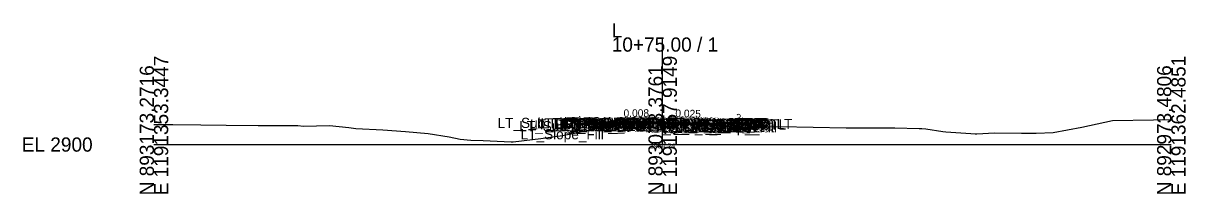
# Model space of a CAD drawing. Extents: x -26 to 203, y -10 to 7027.
# Drawn here: x -25.7 to 202.8, y 1490.3 to 1523.9 of the extents above; entities that cross this region are included whole.
import ezdxf

# ---------------------------------------------------------------- set-up
doc = ezdxf.new("R2010")
doc.units = 0
for name, color, linetype in [('Default', 7, 'Continuous'), ('Exist CMT Pavement', 7, 'Continuous'), ('Exist Cross Section Cell', 7, 'Continuous'), ('Exist XS Center Line Elevation Label', 7, 'Continuous'), ('Exist XS Ground Line', 7, 'Continuous'), ('Prop CMT Concrete Structures', 7, 'Continuous'), ('Prop CMT Pvmt Course 1', 7, 'Continuous'), ('Prop CMT Pvmt Course 2', 7, 'Continuous'), ('Prop CMT Pvmt Course 2 Wedge', 7, 'Continuous'), ('Prop CMT Pvmt Course 3', 7, 'Continuous'), ('Prop CMT Pvmt Course 3 Wedge', 7, 'Continuous'), ('Prop CMT Pvmt Surface', 7, 'Continuous'), ('Prop CMT Pvmt Surface Shoulder', 7, 'Continuous'), ('Prop CMT Pvmt Wedge Surface 3', 7, 'Continuous'), ('Prop CMT Shld Paved Course 1', 7, 'Continuous'), ('Prop CMT Shld Paved Course 2', 7, 'Continuous'), ('Prop CMT Shld Paved Course 3', 7, 'Continuous'), ('Prop CMT Slope Grass', 7, 'Continuous'), ('Prop CMT Subgrade Earthwork', 7, 'Continuous'), ('Scratch_Level_6', 7, 'Continuous')]:
    doc.layers.add(name, color=color, linetype=linetype)

msp = doc.modelspace()

# ---------------------------------------------------------------- linework, layer by layer
at = {"layer": 'Exist CMT Pavement'}
for points in [[(89.88, 1504.19), (88.67, 1504.18), (88.46, 1503.97)], [(88.46, 1503.97), (89.88, 1503.98)], [(89.88, 1503.98), (89.88, 1504.19)], [(100, 1504.24), (91.04, 1504.19)], [(91.04, 1504.19), (95.52, 1504.21)], [(95.52, 1504.21), (100, 1504.24)], [(104.73, 1504.09), (100, 1504.24)], [(100, 1504.24), (109.47, 1503.95)], [(109.47, 1503.95), (104.73, 1504.09)], [(110.13, 1504.02), (111.34, 1503.99), (111.55, 1503.78)], [(110.13, 1503.81), (110.13, 1504.02)], [(111.55, 1503.78), (110.13, 1503.81)]]:
    msp.add_lwpolyline(points, dxfattribs=at)
at = {"layer": 'Exist Cross Section Cell'}
for p, q in [((100, 1500), (100, 1521.09)), ((0, 1500), (100, 1500)), ((100, 1500), (200, 1500))]:
    msp.add_line(p, q, dxfattribs=at)
at = {"layer": 'Exist XS Center Line Elevation Label'}
for points in [[(100, 1504.27), (91.04, 1504.2)], [(100, 1504.27), (109.47, 1504.04)]]:
    msp.add_lwpolyline(points, dxfattribs=at)
at = {"layer": 'Exist XS Ground Line'}
for points in [[(100, 1504.36), (91.04, 1504.28)], [(100, 1504.36), (109.47, 1504.12)]]:
    msp.add_lwpolyline(points, dxfattribs=at)
at = {"layer": 'Prop CMT Concrete Structures'}
for points in [[(100, 1504.48), (89.88, 1504.4)], [(100, 1504.48), (110.13, 1504.23)]]:
    msp.add_lwpolyline(points, dxfattribs=at)
at = {"layer": 'Prop CMT Pvmt Course 1'}
for points in [[(100, 1504.48), (89.88, 1504.4)], [(89.88, 1504.4), (89.88, 1504.19)], [(89.88, 1504.19), (91.04, 1504.2)], [(91.04, 1504.2), (89.88, 1504.19)], [(89.88, 1504.19), (89.88, 1503.98)], [(89.88, 1503.98), (91.04, 1503.99)], [(91.04, 1504.28), (100, 1504.36)], [(91.04, 1504.2), (91.04, 1504.28)], [(91.04, 1503.99), (91.04, 1504.2)], [(100, 1504.27), (100, 1504.48)], [(100, 1504.48), (110.13, 1504.23)], [(100, 1504.27), (100, 1504.48)], [(100, 1504.36), (100, 1504.27), (100, 1504.27)], [(109.47, 1504.12), (100, 1504.36)], [(100, 1504.36), (100, 1504.27), (100, 1504.27)], [(109.47, 1504.04), (109.47, 1504.12)], [(110.13, 1504.02), (109.47, 1504.04)], [(109.47, 1503.83), (109.47, 1504.04)], [(109.47, 1504.04), (110.13, 1504.02)], [(110.13, 1503.81), (109.47, 1503.83)], [(110.13, 1504.23), (110.13, 1504.02)], [(110.13, 1504.02), (110.13, 1503.81)]]:
    msp.add_lwpolyline(points, dxfattribs=at)
at = {"layer": 'Prop CMT Pvmt Course 2'}
for points in [[(100, 1504.06), (91.04, 1503.99)], [(100, 1504.06), (109.47, 1503.83)]]:
    msp.add_lwpolyline(points, dxfattribs=at)
at = {"layer": 'Prop CMT Pvmt Course 3'}
for points in [[(91.04, 1503.99), (89.88, 1503.98)], [(89.88, 1503.98), (89.88, 1503.65)], [(91.04, 1503.66), (91.04, 1503.99)], [(109.47, 1503.83), (110.13, 1503.81)], [(109.47, 1503.49), (109.47, 1503.83)], [(110.13, 1503.81), (110.13, 1503.48)], [(89.88, 1503.65), (91.04, 1503.66)], [(110.13, 1503.48), (109.47, 1503.49)]]:
    msp.add_lwpolyline(points, dxfattribs=at)
at = {"layer": 'Prop CMT Pvmt Course 3 Wedge'}
for p, q in [((0, 1503.92), (3.7, 1503.97)), ((3.7, 1503.97), (9.2, 1503.91)), ((9.2, 1503.91), (14.23, 1503.81)), ((14.23, 1503.81), (20.5, 1503.78)), ((20.5, 1503.78), (27.45, 1503.73)), ((88.96, 1503.67), (91.04, 1504.19)), ((91.04, 1504.19), (94.71, 1504.21)), ((94.71, 1504.21), (99.89, 1504.24)), ((99.89, 1504.24), (105.8, 1504.06)), ((105.8, 1504.06), (109.47, 1503.95)), ((109.47, 1503.95), (112.43, 1503.58)), ((182.43, 1503.44), (188.44, 1504.74)), ((188.44, 1504.74), (196.51, 1504.89)), ((196.51, 1504.89), (198.34, 1504.91)), ((198.34, 1504.91), (200, 1504.89)), ((27.45, 1503.73), (28.31, 1503.72)), ((28.31, 1503.72), (29.37, 1503.64)), ((29.37, 1503.64), (34.53, 1503.73)), ((34.53, 1503.73), (38.29, 1503.39)), ((38.29, 1503.39), (39.66, 1503.16)), ((39.66, 1503.16), (44.97, 1502.9)), ((44.97, 1502.9), (49.43, 1502.54)), ((49.43, 1502.54), (53.9, 1502.19)), ((53.9, 1502.19), (58.06, 1501.53)), ((58.06, 1501.53), (60.17, 1501.07)), ((76.03, 1501.16), (80.34, 1501.79)), ((80.34, 1501.79), (86.36, 1502.99)), ((86.36, 1502.99), (87.56, 1503.34)), ((87.56, 1503.34), (88.96, 1503.67)), ((112.43, 1503.58), (113.77, 1503.4)), ((113.77, 1503.4), (123.08, 1503.55)), ((123.08, 1503.55), (136.07, 1503.3)), ((136.07, 1503.3), (145.66, 1503.26)), ((145.66, 1503.26), (150.46, 1503.18)), ((150.46, 1503.18), (150.97, 1503.15)), ((150.97, 1503.15), (151.77, 1503.1)), ((151.77, 1503.1), (155.1, 1502.6)), ((155.1, 1502.6), (155.68, 1502.52)), ((155.68, 1502.52), (160.61, 1502.18)), ((160.61, 1502.18), (161.42, 1502.13)), ((161.42, 1502.13), (161.74, 1502.14)), ((161.74, 1502.14), (165.24, 1502.28)), ((165.24, 1502.28), (170.53, 1502.24)), ((170.53, 1502.24), (172.13, 1502.23)), ((172.13, 1502.23), (173.46, 1502.27)), ((173.46, 1502.27), (176.77, 1502.36)), ((176.77, 1502.36), (182.43, 1503.44)), ((60.17, 1501.07), (62.27, 1500.89)), ((62.27, 1500.89), (64.74, 1500.77)), ((64.74, 1500.77), (70.22, 1500.55)), ((70.22, 1500.55), (70.61, 1500.53)), ((70.61, 1500.53), (76.03, 1501.16))]:
    msp.add_line(p, q, dxfattribs=at)
at = {"layer": 'Prop CMT Pvmt Surface'}
for points in [[(88.88, 1504.39), (85.88, 1504.19), (81.56, 1502.03)], [(111.13, 1504.2), (114.13, 1503.96), (115.21, 1503.42)]]:
    msp.add_lwpolyline(points, dxfattribs=at)
at = {"layer": 'Prop CMT Pvmt Surface Shoulder'}
for points in [[(89.88, 1504.4), (88.88, 1504.39)], [(110.13, 1504.23), (111.13, 1504.2)]]:
    msp.add_lwpolyline(points, dxfattribs=at)
at = {"layer": 'Prop CMT Shld Paved Course 1'}
for points in [[(89.88, 1504.4), (88.88, 1504.39), (88.67, 1504.18)], [(88.67, 1504.18), (89.88, 1504.19)], [(89.88, 1504.19), (89.88, 1504.4)], [(89.88, 1504.19), (89.88, 1504.4)], [(91.04, 1504.2), (89.88, 1504.19)], [(100, 1504.36), (91.04, 1504.28)], [(91.04, 1504.28), (91.04, 1504.2)], [(100, 1504.36), (109.47, 1504.12)], [(109.47, 1504.12), (109.47, 1504.04)], [(109.47, 1504.04), (110.13, 1504.02)], [(110.13, 1504.23), (111.13, 1504.2), (111.34, 1503.99)], [(110.13, 1504.02), (110.13, 1504.23)], [(110.13, 1504.02), (110.13, 1504.23)], [(111.34, 1503.99), (110.13, 1504.02)]]:
    msp.add_lwpolyline(points, dxfattribs=at)
at = {"layer": 'Prop CMT Shld Paved Course 2'}
for points in [[(89.88, 1504.19), (89.88, 1504.4)], [(100, 1504.27), (89.88, 1504.19)], [(100, 1504.27), (110.13, 1504.02)], [(110.13, 1504.02), (110.13, 1504.23)]]:
    msp.add_lwpolyline(points, dxfattribs=at)
at = {"layer": 'Prop CMT Shld Paved Course 3'}
for points in [[(89.88, 1503.98), (89.88, 1504.4)], [(100, 1504.06), (89.88, 1503.98)], [(100, 1504.06), (110.13, 1503.81)], [(110.13, 1503.81), (110.13, 1504.23)]]:
    msp.add_lwpolyline(points, dxfattribs=at)
at = {"layer": 'Prop CMT Slope Grass'}
for points in [[(89.88, 1503.98), (88.46, 1503.97), (87.96, 1503.97), (87.62, 1503.63)], [(89.88, 1503.65), (89.88, 1503.98)], [(110.13, 1503.81), (111.55, 1503.78), (112.05, 1503.76), (112.39, 1503.42)], [(110.13, 1503.48), (110.13, 1503.81)], [(87.62, 1503.63), (89.88, 1503.65)], [(112.39, 1503.42), (110.13, 1503.48)]]:
    msp.add_lwpolyline(points, dxfattribs=at)
at = {"layer": 'Prop CMT Subgrade Earthwork'}
for points in [[(87.62, 1503.63), (86.99, 1504.26)], [(91.04, 1503.66), (91.05, 1504.19)], [(109.47, 1503.49), (109.45, 1503.95)], [(112.39, 1503.42), (113.02, 1504.05)], [(89.88, 1503.65), (87.62, 1503.63)], [(91.04, 1503.66), (89.88, 1503.65)], [(109.47, 1503.49), (110.13, 1503.48)], [(110.13, 1503.48), (112.39, 1503.42)]]:
    msp.add_lwpolyline(points, dxfattribs=at)

# ---------------------------------------------------------------- texts
at = {"layer": 'Default'}
msp.add_text('-', height=0.0001, dxfattribs=at).set_placement((0, 1500))
at = {"layer": 'Exist Cross Section Cell'}
for s, p in [('L', (90, 1521.09)), ('10+75.00 / 1', (90, 1518.29)), ('EL 2900', (-26, 1498.6))]:
    msp.add_text(s, height=2.8, dxfattribs=at).set_placement(p)
for s, p in [('N 893173.2716', (0, 1490)), ('E 1191353.3447', (2.8, 1490)), ('N 893073.3761', (100, 1490)), ('E 1191357.9149', (102.8, 1490)), ('N 892973.4806', (200, 1490)), ('E 1191362.4851', (202.8, 1490))]:
    msp.add_text(s, height=2.8, rotation=90, dxfattribs=at).set_placement(p)
at = {"layer": 'Prop CMT Pvmt Course 2 Wedge'}
for s, p in [('LT_Sub_Trench_Out_DLT', (67.55, 1503.26)), ('LT_Sub_Trench_Out', (71.82, 1502.63)), ('LT_PS3_Shelf_Out', (73.94, 1502.97)), ('LT_GS_OS_CTL', (75.25, 1503.19)), ('LT_PV_Sub_Tie_Out', (76, 1503.19)), ('LT_PV_OEEOP_EG', (78.58, 1503.19)), ('LT_PS3_OEOP', (78.69, 1502.97)), ('LT_PS2_OEOP', (78.9, 1503.18)), ('LT_PS1_OEOP', (79.68, 1503.39)), ('LT_Sub_OEOT', (79.95, 1502.65)), ('LT_PV2_OEOT', (80.05, 1503.19)), ('LT_PV3_OEOT', (80.05, 1502.98)), ('LT_Sub_OEEOP', (80.25, 1502.66)), ('LT_PV2_OEEOP', (80.35, 1503.2)), ('LT_PV3_OEEOP', (80.35, 1502.99)), ('LT_PV1_OEOT', (80.62, 1503.4)), ('LT_PV1_OEEOP', (80.91, 1503.28)), ('LT_PV_EG_TestPt', (81.93, 1503.21)), ('RT_PV_IEEOP_EG', (88.14, 1503.24)), ('LT_PV_IEEOP_EG', (88.19, 1503.24)), ('RT_PV2_IEEOP', (89.91, 1503.27)), ('RT_PV3_IEEOP', (89.91, 1503.06)), ('LT_PV2_IEEOP', (89.95, 1503.27)), ('LT_PV3_IEEOP', (89.95, 1503.06)), ('RT_PV1_IEEOP', (90.47, 1503.36)), ('LT_PV1_IEEOP', (90.52, 1503.36)), ('RT_PV_EG_TestPt', (91.1, 1503.09)), ('RT_Sub_Trench_Out_DLT', (93.54, 1503.05)), ('PV2_PGL', (93.91, 1503.27)), ('RT_PV_Sub_Tie_Out', (94.35, 1502.95)), ('PV1_PGL', (94.47, 1503.48)), ('RT_Sub_Trench_Out', (96.55, 1502.42)), ('RT_PV_OEEOP_EG', (96.97, 1502.95)), ('RT_PS3_Shelf_Out', (97.99, 1502.76)), ('RT_Sub_OEEOP', (98.63, 1502.49)), ('RT_PV2_OEEOP', (98.73, 1503.04)), ('RT_PV3_OEEOP', (98.73, 1502.83)), ('RT_PV1_OEEOP', (99.3, 1503.12)), ('RT_Sub_OEOT', (100.16, 1502.48)), ('RT_PV2_OEOT', (100.25, 1503.02)), ('RT_PV3_OEOT', (100.25, 1502.81)), ('RT_PV1_OEOT', (100.82, 1503.23)), ('RT_PS2_OEOP', (101.53, 1502.99)), ('RT_PS3_OEOP', (101.74, 1502.78)), ('RT_PS1_OEOP', (101.88, 1503.2)), ('RT_GS_OS_CTL', (103.45, 1502.96)), ('RT_Slope_Fill', (105.68, 1502.42)), ('LT_Slope_Fill', (72.08, 1501.03))]:
    msp.add_text(s, height=2, dxfattribs=at).set_placement(p)
at = {"layer": 'Prop CMT Pvmt Surface Shoulder'}
for s, rotation, p in [('0.008', 0.4555, (92.32, 1505.42)), ('0.025', 358.5679, (102.49, 1505.42))]:
    msp.add_text(s, height=1.5, rotation=rotation, dxfattribs=at).set_placement(p)
at = {"layer": 'Prop CMT Pvmt Wedge Surface 3'}
for rotation, p in [(333.4349, (113.94, 1504.89)), (26.5651, (82.32, 1503.25))]:
    msp.add_text('2:1', height=1.5, rotation=rotation, dxfattribs=at).set_placement(p)
at = {"layer": 'Scratch_Level_6'}
msp.add_text('2904.24', height=1, dxfattribs=at).set_placement((97.47, 1499.24))

doc.saveas('drawing.dxf')
